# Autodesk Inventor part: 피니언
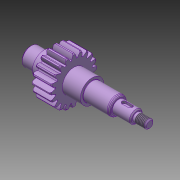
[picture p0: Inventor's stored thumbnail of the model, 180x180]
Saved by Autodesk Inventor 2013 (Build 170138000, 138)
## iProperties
Created: 2019-06
Part Number: 피니언
Material: 스테인리스강
Document SubType Name: Modeling
Designer: mduedu
Density: 1 g/cm^3
Author: mduedu
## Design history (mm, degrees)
sketch "스케치1"
  geometry: L1 (0, 0)-(13, 0); L2 (13, 0)-(13, 8.5); L3 (13, 8.5)-(0, 8.5); L4 (0, 8.5)-(0, 0); L5 (13, 0)-(58, 0); L6 (58, 0)-(58, 11); L7 (58, 11)-(13, 11); L8 (13, 11)-(13, 0); L9 (58, 0)-(83, 0); L10 (83, 0)-(83, 8.5); L11 (83, 8.5)-(58, 8.5); L12 (58, 8.5)-(58, 0); L13 (83, 0)-(100, 0); L14 (100, 0)-(100, 6); L15 (100, 6)-(83, 6); L16 (83, 6)-(83, 0); L17 (100, 0)-(112, 0); L18 (112, 0)-(112, 4); L19 (112, 4)-(100, 4); L20 (100, 4)-(100, 0)
  constraints: 40 end point, 10 parallel, 5 horizontal, 5 perpendicular
  dimensions: "d0" = 112 distance between parallel lines of L18 L4; "d2" = 83 distance between parallel lines of L10 L4; "d3" = 45 distance of L6.end L7.end; "d4" = 25 distance of L10.end L11.end; "d5" = 17 distance of L14.end L15.end; "d6" = 8 diameter of L19 L17; "d7" = 12 diameter of L15 L13; "d8" = 17 diameter of L11 L9; "d9" = 22 diameter of L7 L5; "d10" = 17 diameter of L3 L1
revolve "회전1" sketch "스케치1" stored, may be unused: angle "d11" = 90 deg
node "작업 평면1"
sketch "스케치2"
  geometry: C1 r 17.5 at (0, 0); C2 r 20 at (0, 0); C3 r 22 at (0, 0); 1 further point
  constraints: 3 centre point, 3 coincident
  dimensions: "d13" = 40 diameter of C2; "d15" = 44 diameter of C3; "d16" = 35 diameter of C1
extrude "돌출1" join sketch "스케치2" distance "d17" = 18; taper "d18" = 0 deg
sketch "스케치3"
  geometry: L1 (0, 0)-(22, 0); L2 (0, 0)-(0, 22); L3 (0.57, 0)-(0.57, 22); L4 (1.57, 0)-(1.57, 22); L5 (2.07, 0)-(2.07, 22); A1 r 22 centre (0, 0) between (22, 0) and (0, 22) reference; A2 r 9.495 centre (-7.411, 16.856) between (2.07, 17.377) and (0.57, 22); A3 r 9.495 centre (7.411, 16.856) between (-0.57, 22) and (-2.07, 17.377); A4 r 17.5 centre (0, 0) between (2.07, 17.377) and (-2.07, 17.377); A5 r 22.007 centre (0, 0) between (0.57, 22) and (-0.57, 22); 4 further points
  constraints: 11 point on circle, 10 end point, 6 parallel, 5 point on line, 4 centre point, 3 symmetric about line, 2 coincident, 1 horizontal, 1 perpendicular, 5 other
  dimensions: "d19" = 0.5 distance between parallel lines of L5 L4; "d21" = 1 distance between parallel lines of L3 L4; "d22" = 1.57 distance between parallel lines of L2 L4
extrude "돌출2" join sketch "스케치3" stored distance "d23" = 18; taper "d24" = 0 deg
chamfer "모따기1" distance "d25" = 1; stored, may be unused: second distance "d26" = 2, angle "d27" = 45 deg
fillet "모깎기1" dims "d31" = 0.3
chamfer "모따기2" distance "d32" = 1; stored, may be unused: second distance "d33" = 2, angle "d34" = 45 deg
node "작업 평면2"
sketch "스케치4"
  geometry: L1 (3.5, -2)-(-2.5, -2); L2 (-2.5, 2)-(3.5, 2); L3 (8.5, 8.5)-(8.5, -8.5) reference; A1 r 2 centre (3.5, 0) between (3.5, -2) and (3.5, 2); A2 r 2 centre (-2.5, 0) between (-2.5, 2) and (-2.5, -2); 1 further point
  constraints: 4 end point, 4 point on circle, 4 tangent, 2 centre point, 1 horizontal, 1 horizontal alignment, 1 parallel
  dimensions: "d35" = 3 distance edge to line of A1 L3; "d36" = 10 dimension on A2 A1; "d37" = 4 distance between parallel lines of L2 L1
extrude "돌출3" cut sketch "스케치4" distance "d38" = 2.5; taper "d39" = 0 deg
chamfer "모따기3" distance "d40" = 1.82; stored, may be unused: second distance "d41" = 2, angle "d42" = 30 deg
fillet "모깎기2" dims "d43" = 1, "d44" = 2
chamfer "모따기4" distance "d45" = 1; stored, may be unused: second distance "d46" = 2, angle "d47" = 30 deg
feature "스레드1" dims "d48" = 10, "d49" = 0
chamfer "모따기5" distance "d50" = 1; stored, may be unused: second distance "d51" = 2, angle "d52" = 30 deg
node "솔리드1"
pattern_circular "원형 패턴1" dims angle "d29" = 360 deg
other parameters: "d12" = -17
